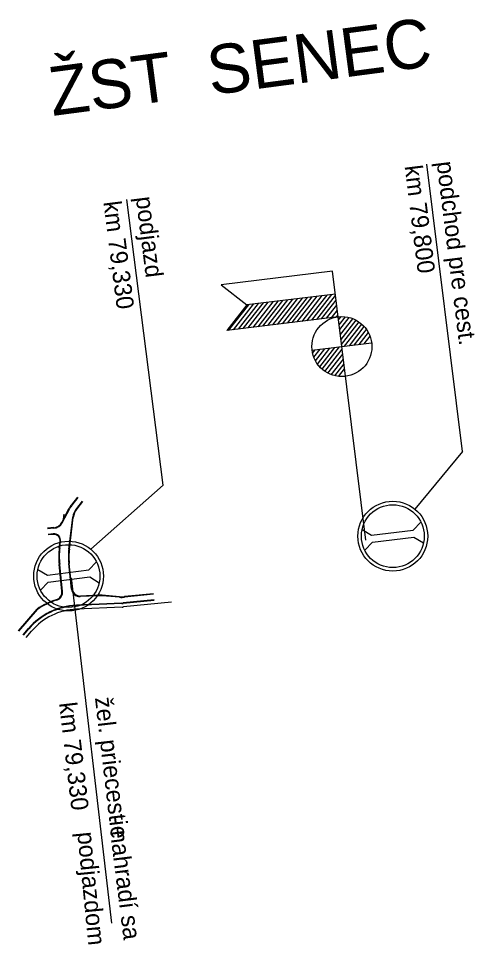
# Model space of a CAD drawing. Extents: x -566241 to -446826, y -1330151 to -1274078.
# Drawn here: x -550806 to -550152, y -1275965 to -1274638 of the extents above; entities that cross this region are included whole.
import ezdxf

# ---------------------------------------------------------------- set-up
doc = ezdxf.new("R2010")
doc.units = 0
doc.layers.add('1-POPIS', color=7, linetype='Continuous')
doc.layers.add('STANICE', color=7, linetype='Continuous')

msp = doc.modelspace()

# ---------------------------------------------------------------- linework, layer by layer
at = {"layer": '1-POPIS'}
for p, q in [((-550169.4, -1275258.4), (-550220.5, -1274846.3)), ((-550598.8, -1275306.7), (-550650.5, -1274897.2)), ((-550169.4, -1275258.4), (-550237.6, -1275341.1)), ((-550598.8, -1275306.7), (-550702.4, -1275398.2)), ((-550721.6, -1275324), (-550729.9, -1275334.7)), ((-550721, -1275324.5), (-550729.3, -1275335.2)), ((-550714.7, -1275329.5), (-550723, -1275340.1)), ((-550714, -1275330), (-550722.2, -1275340.5)), ((-550743.9, -1275360), (-550733.2, -1275339.8)), ((-550743.2, -1275360.4), (-550732.5, -1275340.1)), ((-550741.6, -1275355.2), (-550740.7, -1275348.3)), ((-550733.8, -1275398.2), (-550728.1, -1275352.5)), ((-550733, -1275398.2), (-550727.4, -1275352.8)), ((-550240.2, -1275371), (-550229.1, -1275359.6)), ((-550755.1, -1275367.5), (-550764.3, -1275368.4)), ((-550755.1, -1275368.3), (-550764.2, -1275369.2)), ((-550313.3, -1275370), (-550299.8, -1275378.4)), ((-550299.8, -1275378.4), (-550240.2, -1275371)), ((-550756.2, -1275376.5), (-550763.5, -1275377.1)), ((-550756.1, -1275377.3), (-550763.4, -1275377.9)), ((-550747.5, -1275396.5), (-550746.3, -1275387.3)), ((-550746.7, -1275396.6), (-550745.6, -1275387.4)), ((-550298.6, -1275388.3), (-550309.7, -1275399.8)), ((-550298.6, -1275388.3), (-550239, -1275380.9)), ((-550239, -1275380.9), (-550225.4, -1275389.3)), ((-550778.2, -1275427.3), (-550764.6, -1275435.7)), ((-550764.6, -1275435.7), (-550705.1, -1275428.1)), ((-550743.7, -1275458.2), (-550747.7, -1275420.2)), ((-550742.8, -1275458.7), (-550746.9, -1275420.1)), ((-550730.1, -1275455.6), (-550734, -1275418.7)), ((-550729.3, -1275454.7), (-550733.2, -1275418.7)), ((-550705.1, -1275428.1), (-550694, -1275416.7)), ((-550763.3, -1275445.6), (-550703.8, -1275438.1)), ((-550730.3, -1275439.2), (-550672.4, -1275934.2)), ((-550703.8, -1275438.1), (-550690.2, -1275446.4)), ((-550763.3, -1275445.6), (-550774.4, -1275457.1)), ((-550691.2, -1275465.1), (-550717.6, -1275466.3)), ((-550691.2, -1275464.3), (-550716.9, -1275465.5)), ((-550661.2, -1275466.5), (-550686.1, -1275464.4)), ((-550661.2, -1275467.3), (-550686.1, -1275465.2)), ((-550612.3, -1275462.2), (-550653.8, -1275466.4)), ((-550612.3, -1275463), (-550653.8, -1275467.2)), ((-550658, -1275475.6), (-550723, -1275478.5)), ((-550657.9, -1275476.4), (-550723, -1275479.3)), ((-550657.5, -1275481.4), (-550722.8, -1275484.3)), ((-550611.5, -1275471), (-550655.8, -1275475.4)), ((-550611.4, -1275471.8), (-550655.7, -1275476.2)), ((-550586.7, -1275474.3), (-550655.3, -1275481.2)), ((-550805.9, -1275515.3), (-550779.4, -1275484.2)), ((-550805.3, -1275515.8), (-550778.8, -1275484.8)), ((-550799.2, -1275521), (-550791.6, -1275512.1)), ((-550798.6, -1275521.6), (-550791, -1275512.6)), ((-550794.8, -1275524.8), (-550787.2, -1275515.9))]:
    msp.add_line(p, q, dxfattribs=at)
for centre, radius in [((-550269.4, -1275379.7), 50), ((-550269.4, -1275379.7), 45), ((-550734.2, -1275436.9), 50), ((-550734.2, -1275436.9), 45)]:
    msp.add_circle(centre, radius, dxfattribs=at)
for centre, radius, start, end in [((-550703.3, -1275355.5), 33.8, 141.944, 152.1714), ((-550703.3, -1275355.5), 33, 141.944, 152.1714), ((-550703.3, -1275355.5), 25, 141.944, 172.9543), ((-550702.6, -1275355.9), 25, 141.944, 172.9543), ((-550756.5, -1275353.4), 14.2, 275.3301, 332.1714), ((-550756.5, -1275353.4), 15, 275.3301, 332.1714), ((-550755.3, -1275386.2), 9.8, 352.9543, 95.3301), ((-550755.3, -1275386.2), 9, 352.9543, 95.3301), ((-550644.5, -1275409.2), 103.8, 172.9543, 186.0543), ((-550644.5, -1275409.2), 103, 172.9543, 186.0543), ((-550644.5, -1275409.2), 90, 172.9543, 186.0543), ((-550643.7, -1275409.2), 90, 172.9543, 186.0543), ((-550717.4, -1275453.5), 12, 186.0543, 272.5942), ((-550755.6, -1275459.4), 12, 287.8083, 6.0543), ((-550754.7, -1275460), 12, 287.4973, 6.0543), ((-550718.1, -1275454.3), 12, 186.0543, 272.5942), ((-550689.4, -1275504.2), 40, 85.2462, 92.5942), ((-550689.4, -1275505), 40, 85.2462, 92.5942), ((-550657.8, -1275426.6), 40, 265.2462, 275.7551), ((-550657.8, -1275427.4), 40, 265.2462, 275.7551), ((-550718.7, -1275574.2), 95.8, 92.5942, 139.5614), ((-550718.7, -1275574.2), 95, 92.5942, 139.5614), ((-550718.7, -1275574.2), 108.6, 107.8083, 123.9624), ((-550718.7, -1275574.2), 107.8, 107.4973, 123.9043), ((-550659.8, -1275435.6), 40, 272.5942, 275.7551), ((-550659.7, -1275436.4), 40, 272.5942, 275.7551), ((-550659.3, -1275441.4), 40, 272.5942, 275.7551), ((-550718.7, -1275574.2), 90, 92.5942, 139.5614)]:
    msp.add_arc(centre, radius, start, end, dxfattribs=at)
at = {"layer": 'STANICE'}
for p, q in [((-550355.8, -1274999.8), (-550515.2, -1275019.6)), ((-550308, -1275385.4), (-550355.8, -1274999.8)), ((-550515.2, -1275019.6), (-550478.4, -1275048.3)), ((-550351.7, -1275032.6), (-550478.4, -1275048.3)), ((-550469.6, -1275080.5), (-550440.9, -1275043.6)), ((-550462.6, -1275079.6), (-550433.9, -1275042.8)), ((-550455.6, -1275078.7), (-550426.9, -1275041.9)), ((-550448.6, -1275077.8), (-550419.9, -1275041)), ((-550441.5, -1275077), (-550412.8, -1275040.2)), ((-550434.5, -1275076.1), (-550405.8, -1275039.3)), ((-550427.5, -1275075.2), (-550398.8, -1275038.4)), ((-550420.5, -1275074.4), (-550391.8, -1275037.6)), ((-550413.5, -1275073.5), (-550384.8, -1275036.7)), ((-550406.5, -1275072.6), (-550377.8, -1275035.8)), ((-550399.4, -1275071.8), (-550370.7, -1275034.9)), ((-550392.4, -1275070.9), (-550363.7, -1275034.1)), ((-550385.4, -1275070), (-550356.7, -1275033.2)), ((-550378.4, -1275069.2), (-550351.5, -1275034.6)), ((-550371.4, -1275068.3), (-550350.6, -1275041.6)), ((-550478.4, -1275048.3), (-550507.1, -1275085.1)), ((-550504.7, -1275084.8), (-550476, -1275048)), ((-550497.7, -1275083.9), (-550469, -1275047.1)), ((-550490.7, -1275083.1), (-550462, -1275046.2)), ((-550483.7, -1275082.2), (-550454.9, -1275045.4)), ((-550476.6, -1275081.3), (-550447.9, -1275044.5)), ((-550364.4, -1275067.4), (-550349.7, -1275048.6)), ((-550364.4, -1275067.4), (-550349.7, -1275048.6)), ((-550357.3, -1275066.6), (-550348.8, -1275055.7)), ((-550357.3, -1275066.6), (-550348.8, -1275055.7)), ((-550347.6, -1275065.4), (-550507.1, -1275085.1)), ((-550350.3, -1275065.7), (-550348, -1275062.7)), ((-550350.3, -1275065.7), (-550348, -1275062.7)), ((-550347.1, -1275069.7), (-550343.5, -1275065)), ((-550346.2, -1275076.7), (-550337.4, -1275065.3)), ((-550345.4, -1275083.7), (-550331.8, -1275066.3)), ((-550344.5, -1275090.7), (-550326.7, -1275068)), ((-550343.6, -1275097.8), (-550322.1, -1275070.1)), ((-550342.8, -1275104.8), (-550317.8, -1275072.7)), ((-550338.6, -1275107.6), (-550313.8, -1275075.8)), ((-550331.6, -1275106.7), (-550310.3, -1275079.4)), ((-550324.6, -1275105.8), (-550307.1, -1275083.4)), ((-550317.6, -1275105), (-550304.3, -1275088)), ((-550310.5, -1275104.1), (-550302, -1275093.2)), ((-550385.1, -1275113.3), (-550299.7, -1275102.8)), ((-550377.4, -1275133), (-550359.7, -1275110.2)), ((-550374.2, -1275137), (-550352.6, -1275109.3)), ((-550370.6, -1275140.5), (-550345.6, -1275108.4)), ((-550384.3, -1275117.4), (-550380.7, -1275112.8)), ((-550382.6, -1275123.3), (-550373.7, -1275111.9)), ((-550380.2, -1275128.4), (-550366.7, -1275111.1)), ((-550366.6, -1275143.5), (-550341.9, -1275111.8)), ((-550362.3, -1275146.1), (-550341, -1275118.8)), ((-550357.6, -1275148.3), (-550340.2, -1275125.8)), ((-550352.5, -1275149.8), (-550339.3, -1275132.8)), ((-550347, -1275150.8), (-550338.4, -1275139.9))]:
    msp.add_line(p, q, dxfattribs=at)
msp.add_circle((-550342.4, -1275108), 43, dxfattribs=at)

# ---------------------------------------------------------------- texts
at = {"layer": '1-POPIS'}
for s, rotation, p in [('podchod pre cest.', 277.0678, (-550206.7, -1274843.6)), ('km 79,800', 277.0678, (-550252.5, -1274849.4)), ('podjazd', 277.19, (-550637.9, -1274894.1)), ('km 79,330', 277.19, (-550684.3, -1274900.8)), ('žel. priecestie', 276.6746, (-550696.4, -1275611.5)), ('km 79,330', 276.6746, (-550747.9, -1275619)), ('- nahradí sa', 277.19, (-550677.4, -1275782.3)), ('podjazdom', 275.6045, (-550721.7, -1275804.4))]:
    msp.add_text(s, height=25, rotation=rotation, dxfattribs=at).set_placement(p)
at = {"layer": 'STANICE'}
msp.add_text('ŽST  SENEC', height=70, rotation=7.5115, dxfattribs=at).set_placement((-550757.4, -1274777.5))

doc.saveas('drawing.dxf')
